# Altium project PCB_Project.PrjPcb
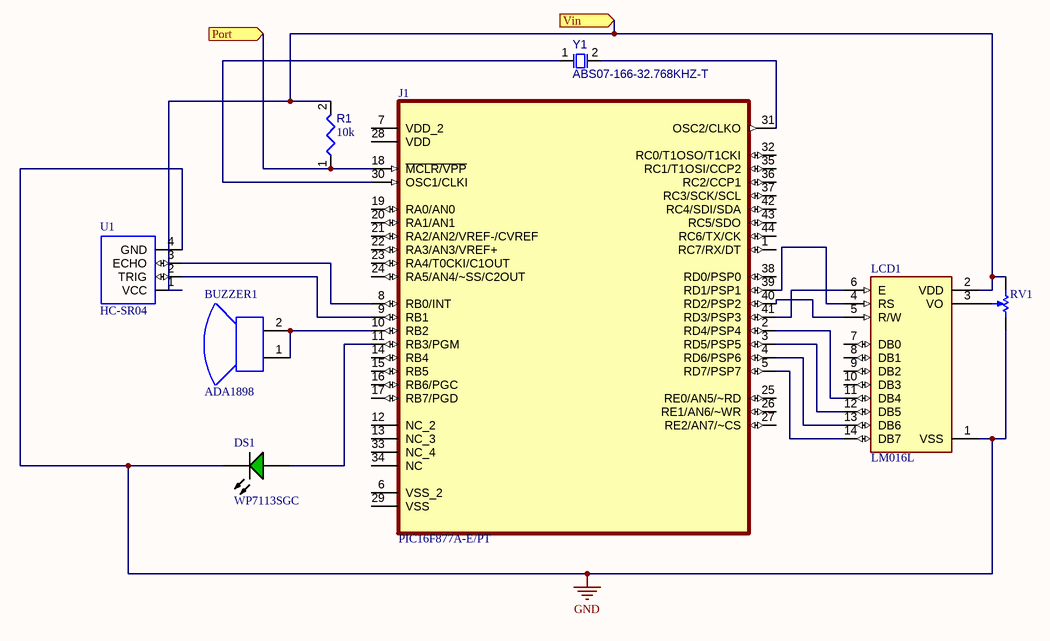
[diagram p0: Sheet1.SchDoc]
CAGE_CODE: ?????; CONTRACT_NUMBER: <CONTRACT NO>; DOC_NO_ASSY_DWG: <ASSY DWG NO>; DOC_NO_BOM: <BOM DOC NO>; DOC_NO_FAB_DWG: <FAB DWG NO>; DOC_NO_SCH_DWG: <SCH DWG NO>; PCB_2_DEC_TOL: +/-.01; PCB_3_DEC_TOL: +/-.010; PCB_ANG_TOL: +/-1/2; PCB_ASSEMBLY_NO: <PCB ASSY NO>; PCB_CHECKER: - -----; PCB_CHECKER_APP_DATE: --/--/----; PCB_DESIGNER: - -----; PCB_DESIGNER_APP_DATE: --/--/----; PCB_DWG_NO: <PCB DWG NO>; PCB_ENGINEER: - -----; PCB_ENGINEER_APP_DATE: --/--/----; PCB_PART_NUMBER: <PCB PN>; PCB_REV: A; SCH_REV: A
1 sheet, 8 parts. Net scope: flat (ports and power ports of the same name join across sheets).
Board file: PCB1.PcbDoc

## Sheet Sheet1.SchDoc
size 431 x 279 mm; SheetNumber: 1; SheetTotal: 1; ENG_APP_DATE: --/--/--; DSN_APP_DATE: --/--/--; CHK_APP_DATE: --/--/--

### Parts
BUZZER1  ADA1898  [ADAI-ADA1898]
DS1  WP7113SGC  [KING-WP7113SGC_V]
J1  PIC16F877A-E/PT  [QFP80P1200X1200X120-44N]
LCD1  LM016L  [LCD_LM016L]
R1  value 10k  [RESC3216X60X45ML15T20]  (hidden comment: Resistor 10k +/-1% 1206 250 mW)
RV1  TC33X-2-103E  [BOUR-TC33X-2_V]  (value not drawn)
U1  HC-SR04  [XCVR_HC-SR04]
Y1  ABS07-166-32.768KHZ-T  [EPSON-FC-135_V]

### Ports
Port (in), Vin (in)

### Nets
GND: DS1.2(K) LCD1.1(VSS) RV1.3 U1.4(GND)
NetBUZZER1_1: BUZZER1.1(+) BUZZER1.2(-) J1.10(RB2)
NetDS1_1: DS1.1(A) J1.11(RB3/PGM)
NetJ1_2: J1.2(RD4/PSP4) LCD1.11(DB4)
NetJ1_3: J1.3(RD5/PSP5) LCD1.12(DB5)
NetJ1_4: J1.4(RD6/PSP6) LCD1.13(DB6)
NetJ1_5: J1.5(RD7/PSP7) LCD1.14(DB7)
NetJ1_8: J1.8(RB0/INT) U1.3(ECHO)
NetJ1_9: J1.9(RB1) U1.2(TRIG)
NetJ1_18: J1.18(~{MCLR/VPP}) R1.1 ; port Port
NetJ1_30: J1.30(OSC1/CLKI) Y1.1
NetJ1_31: J1.31(OSC2/CLKO) Y1.2
NetJ1_39: J1.39(RD1/PSP1) LCD1.4(RS)
NetJ1_40: J1.40(RD2/PSP2) LCD1.5(R/W)
NetJ1_41: J1.41(RD3/PSP3) LCD1.6(E)
NetLCD1_2: LCD1.2(VDD) R1.2 RV1.1 U1.1(VCC) ; port Vin
NetLCD1_3: LCD1.3(VO) RV1.2

Not connected (* = marked no-connect by the designer): J1 1(RC7/RX/DT) 6(VSS_2) 7(VDD_2) 12(NC_2) 13(NC_3) 14(RB4) 15(RB5) 16(RB6/PGC) 17(RB7/PGD) 19(RA0/AN0) 20(RA1/AN1) 21(RA2/AN2/VREF-/CVREF) 22(RA3/AN3/VREF+) 23(RA4/T0CKI/C1OUT) 24(RA5/AN4/~SS/C2OUT) 25(RE0/AN5/~RD) 26(RE1/AN6/~WR) 27(RE2/AN7/~CS) 28(VDD) 29(VSS) 32(RC0/T1OSO/T1CKI) 33(NC_4) 34(NC) 35(RC1/T1OSI/CCP2) 36(RC2/CCP1) 37(RC3/SCK/SCL) 38(RD0/PSP0) 42(RC4/SDI/SDA) 43(RC5/SDO) 44(RC6/TX/CK); LCD1 7(DB0) 8(DB1) 9(DB2) 10(DB3)

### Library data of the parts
BUZZER1 = CMP-00027-00000-1: Mini Speaker, 8 Ohm, 0.2 Wmax, -10 to 40 degC, 2-Pin THD, RoHS; Manufacturer: Adafruit Industries
DS1 = CMP-007-00032-2: The Super Bright Green Source Color Device, 2.2 V, -40 to 85 degC, 2-Pin THD, RoHS, Tape and Reel; Manufacturer: Kingbright; Luminous Intensity: 200mcd; Nominal Vf: 2.2V; Viewing Angle: 20degrees; Lens Style: Clear
J1 = PIC16F877A-E/PT: 7 KB Flash, 368 RAM, 33 I/O44 TQFP 10x10x1mm TRAY ¦ Microchip Technology Inc. PIC16F877A-E/PT
LCD1 = LM016L: Display Lcd 35x75mm; MF: Hitachi
R1 = CMP-009-00016-5: Chip Resistor, 10 KOhm, +/- 1%, 0.25 W, -55 to 155 degC, 1206 (3216 Metric); Power: 250mW; Voltage Rating: 200V
RV1 = CMP-009-00060-2: Trimming Potentiometer, 1000 Ohm, -40 to 100 degC, 3-Pin SMD, RoHS, Tape and Reel; Manufacturer: Bourns; Tolerance: 25%; Power: 100mW; Resistance: 10k
U1 = HC-SR04: Ultrasonic Sensor Module
Y1 = CMP-003-00029-1: Crystal 32.768kHz 10ppm 7pF -40C +85C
